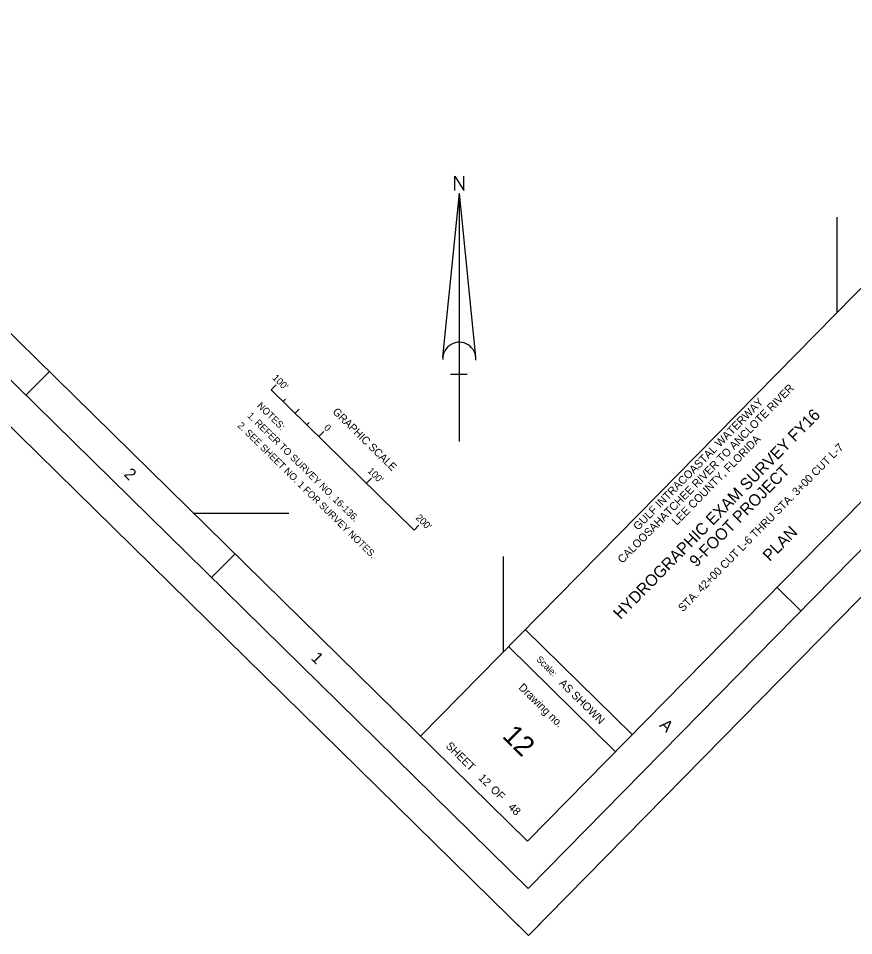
# Model space of a CAD drawing. Extents: x 614899 to 620420, y 778867 to 784376.
# Drawn here: x 617273 to 618525, y 778867 to 780242 of the extents above; entities that cross this region are included whole.
import ezdxf

# ---------------------------------------------------------------- set-up
doc = ezdxf.new("R2010")
doc.units = 0
for name, color, linetype in [('G-ANNO-NPLT', 7, 'Continuous'), ('G-ANNO-TEXT-DRWG', 7, 'Continuous'), ('G-ANNO-TEXT-PROJ', 7, 'Continuous'), ('G-ANNO-TEXT-TTLB', 7, 'Continuous'), ('G-ANNO-TTLB', 7, 'Continuous'), ('V-ANNO-NOTE', 7, 'Continuous'), ('V-ANNO-SYMB', 7, 'Continuous'), ('V-TOPO-COOR-STAT', 7, 'Continuous')]:
    doc.layers.add(name, color=color, linetype=linetype)

msp = doc.modelspace()

# ---------------------------------------------------------------- linework, layer by layer
at = {"layer": 'G-ANNO-NPLT'}
msp.add_lwpolyline([(617282, 784375.7), (620420.5, 781292), (618037.6, 778866.8), (614899.1, 781950.5)], close=True, dxfattribs=at)
msp.add_lwpolyline([(618072.7, 778902.3), (618037.7, 778866.7), (618002, 778901.7)], dxfattribs=at)
at = {"layer": 'G-ANNO-TTLB'}
for p, q in [((620118.6, 781448.4), (617875.8, 779165.9)), ((617284.4, 779676.9), (617319.5, 779712.5)), ((617562.6, 779403.5), (617597.7, 779439.2)), ((618445.8, 779353.5), (618410.1, 779388.6)), ((618032.6, 779325.5), (618193.2, 779167.8)), ((618007.6, 779300), (618168.1, 779142.3))]:
    msp.add_line(p, q, dxfattribs=at)
for points in [[(614969.8, 781951.2), (618036.9, 778937.5), (620349.8, 781291.3), (617282.6, 784305)], [(620279.1, 781290.7), (617336.7, 784181.8), (615094, 781899.2), (618036.3, 779008.2)]]:
    msp.add_lwpolyline(points, close=True, dxfattribs=at)
at = {"layer": 'V-ANNO-NOTE'}
for p, q in [((617652, 779685), (617659.3, 779692.5)), ((617652, 779685), (617866, 779474.8)), ((617669.8, 779667.5), (617673.2, 779670.9)), ((617687.7, 779650), (617693.6, 779656)), ((617705.5, 779632.5), (617708.9, 779635.9)), ((617723.3, 779614.9), (617730.6, 779622.4)), ((617723.3, 779614.9), (617730.6, 779622.4)), ((617723.3, 779614.9), (617726.8, 779618.5)), ((617794.7, 779544.8), (617802, 779552.3)), ((617866, 779474.8), (617873.3, 779482.2))]:
    msp.add_line(p, q, dxfattribs=at)
at = {"layer": 'V-ANNO-SYMB'}
for p, q in [((617909.2, 779733.9), (617933.9, 779979.7)), ((617933.9, 779607.4), (617933.9, 779979.7)), ((617958.6, 779733.9), (617933.9, 779979.7)), ((617945.6, 779707.9), (617920.8, 779707.9))]:
    msp.add_line(p, q, dxfattribs=at)
msp.add_lwpolyline([(617927, 779983.7), (617927, 780005.4), (617940.5, 779983.7), (617940.5, 780005.4)], dxfattribs=at)
msp.add_arc((617933.9, 779731.5), 24.8, 355.2984, 182.0673, dxfattribs=at)
at = {"layer": 'V-TOPO-COOR-STAT'}
for p, q in [((618500, 779801.2), (618500, 779943.8)), ((617535.8, 779500), (617678.5, 779500)), ((618000, 779292.3), (618000, 779435))]:
    msp.add_line(p, q, dxfattribs=at)

# ---------------------------------------------------------------- texts
at = {"layer": 'G-ANNO-TEXT-DRWG'}
for s, height, rotation, p in [('STA. 42+00 CUT L-6 THRU STA. 3+00 CUT L-7', 12, 45.5037, (618269, 779351.4)), ('PLAN', 17.5, 45.5037, (618399.2, 779426.6)), ('12', 30, 315.5037, (617996.9, 779164.4)), (' 12          48', 12, 315.5037, (617958.4, 779105.1))]:
    msp.add_text(s, height=height, rotation=rotation, dxfattribs=at).set_placement(p)
at = {"layer": 'G-ANNO-TEXT-PROJ'}
for s, height, p in [('CALOOSAHATCHEE RIVER TO ANCLOTE RIVER', 12, (618178.4, 779423.9)), ('GULF INTRACOASTAL WATERWAY', 12, (618201.8, 779473.4)), ('HYDROGRAPHIC EXAM SURVEY FY16', 17.5, (618175.3, 779339.7)), ('LEE COUNTY, FLORIDA', 12, (618259.7, 779481)), ('9-FOOT PROJECT', 17.5, (618289.2, 779418.2))]:
    msp.add_text(s, height=height, rotation=45.5037, dxfattribs=at).set_placement(p)
at = {"layer": 'G-ANNO-TEXT-TTLB'}
for s, height, p in [('Scale:', 10, (618048.4, 779280)), ('Drawing no.', 12, (618021.7, 779237.6)), ('AS SHOWN', 12, (618082.3, 779244.1)), ('SHEET         OF', 12, (617912.7, 779150))]:
    msp.add_text(s, height=height, rotation=315.5037, dxfattribs=at).set_placement(p)
at = {"layer": 'G-ANNO-TTLB'}
for s, p in [('2', (617430.1, 779557.1)), ('1', (617710.6, 779281.5)), ('A', (618233, 779181.1))]:
    msp.add_text(s, height=17.5, rotation=315.5037, dxfattribs=at).set_placement(p)
at = {"layer": 'V-ANNO-NOTE'}
for s, height, p in [("100'", 10.42, (617652.9, 779702)), ('NOTES:', 10.42, (617629.9, 779660.1)), ('GRAPHIC SCALE', 11.666, (617743, 779650.9)), ('1. REFER TO SURVEY NO. 16-136.', 10.416, (617615.3, 779645.2)), ('2. SEE SHEET NO. 1 FOR SURVEY NOTES.', 10.416, (617600.7, 779630.4)), ('0', 10.4, (617730.1, 779627.1)), ("100'", 10.42, (617795.5, 779562.4)), ("200'", 10.42, (617867.7, 779492.3))]:
    msp.add_text(s, height=height, rotation=315.5037, dxfattribs=at).set_placement(p)

doc.saveas('drawing.dxf')
